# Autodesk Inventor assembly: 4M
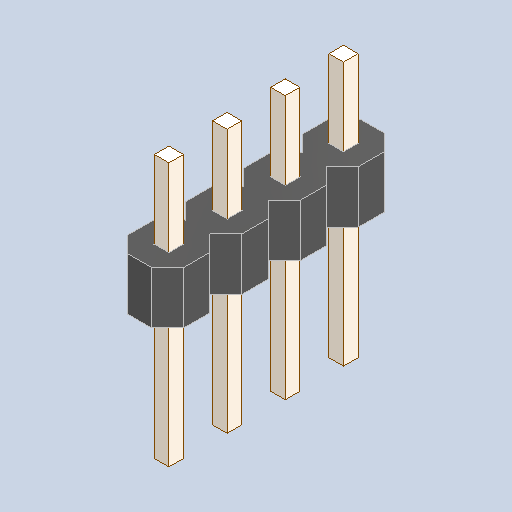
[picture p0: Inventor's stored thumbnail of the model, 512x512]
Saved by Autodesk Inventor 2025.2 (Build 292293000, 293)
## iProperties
Created: 2025-04
Part Number: 4M
Description: PART--DESC
Document SubType Name: Assembly
Designer: BennF
Author: BennF
Revision Number: NONE
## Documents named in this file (3)
- C:\Users\BennF\Nextcloud\Benutzer\CNC JarBeRi\existing parts\Electronics\RepRap A4988 Shied (USE WITHOUT ARDUINO)\reprap-a4988-1.snapshot.1\RepRap\RepRap\4M_3.iam
- C:\Users\BennF\Nextcloud\Benutzer\CNC JarBeRi\existing parts\Electronics\RepRap A4988 Shied (USE WITHOUT ARDUINO)\reprap-a4988-1.snapshot.1\RepRap\RepRap\4M Geometry.ipt
- C:\Users\BennF\Nextcloud\Benutzer\CNC JarBeRi\existing parts\Electronics\RepRap A4988 Shied (USE WITHOUT ARDUINO)\reprap-a4988-1.snapshot.1\RepRap\RepRap\Pin5.ipt
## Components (2 placed, 2 different names)
1. 4M Geometry
2. Pin5
